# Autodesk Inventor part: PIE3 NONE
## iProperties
Shininess: 64.0
Length Units: 11269
Angle Units: 11279
Time Units: 11290
Mass Units: 11286
Length Display Precision: 3
Angle Display Precision: 2
Compacted: True
Part Number: PIE3 NONE
Document SubType Name: Modeling
Created: 2004-08
Designer: John Blackburn
Manufacturer: Standard
Standards Organization: Custom
Density: 0.0
Volumn: 0.0
Area: 0.0
PropertySet Name: Model Information
Control State: 0
Master: False
Checked Out: False
Author: John Blackburn
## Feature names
1. Erst1
